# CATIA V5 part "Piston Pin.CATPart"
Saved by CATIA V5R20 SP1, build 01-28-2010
Part number: Piston Pin
Bounding box of the stored display mesh (mm): x -11 to 11, y -10.833 to 10.833, z -40 to 40
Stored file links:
  D:\v5_r20\psrt_files_downloaded\c13-catia-v5r20-prt\c13-catia-v5r20-figr-13-41\Part & Asm files\Piston Pin.CATPart
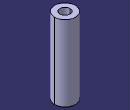
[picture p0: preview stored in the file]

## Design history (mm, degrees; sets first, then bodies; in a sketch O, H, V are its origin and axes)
Body1 (main body)
  Sketch1 on xy-plane, origin (0, 0, 0), H (1, 0, 0), V (0, 1, 0)
    circle A1 centre (0, 0) radius 5.5
    circle A2 centre (0, 0) radius 11
    point P1 (0, 0)
    radius A2 = 11
    radius A1 = 5.5
    coincidence: P1 H
    concentricity: A1 A2
  Pad1: profile Sketch1, direction (0, 0, 1), length 40, mirrored extent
